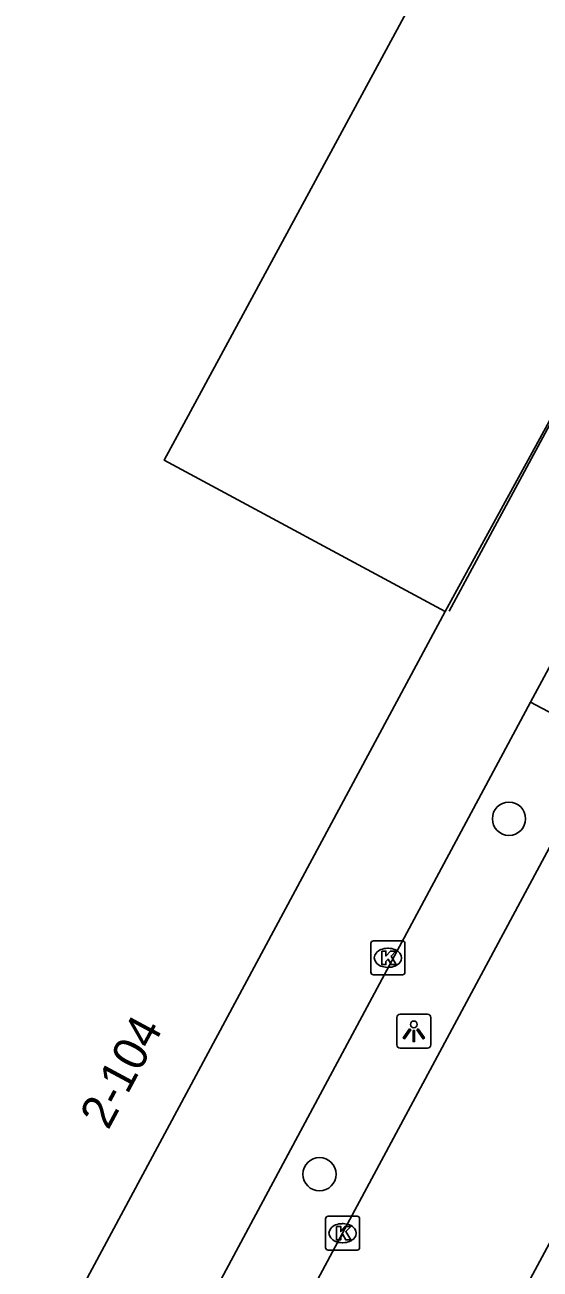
# Model space of a CAD drawing. Extents: x 159489 to 160304, y 383826 to 384530.
# Drawn here: x 159614.71 to 159629.86, y 384181.95 to 384218.51 of the extents above; entities that cross this region are included whole.
import ezdxf

# ---------------------------------------------------------------- set-up
doc = ezdxf.new("R2010")
doc.units = 0
for name, color, linetype in [('IMGEO_Boom', 7, 'Continuous'), ('IMGEO_Kolk', 7, 'Continuous'), ('IMGEO_Lichtpunt', 7, 'Continuous'), ('IMGEO_Lijnafwatering', 7, 'Continuous'), ('IMGEO_Pand', 7, 'Continuous'), ('IMGEO_Pand_nummerreeks', 7, 'Continuous'), ('IMGEO_Rijbaan_lokaal_gesloten', 7, 'Continuous'), ('IMGEO_Voetpad_open', 7, 'Continuous')]:
    doc.layers.add(name, color=color, linetype=linetype)

msp = doc.modelspace()

# ---------------------------------------------------------------- linework, layer by layer
at = {"layer": 'IMGEO_Boom'}
for centre in [(159628.945, 384195.185), (159623.374, 384184.738)]:
    msp.add_circle(centre, 0.489, dxfattribs=at)
at = {"layer": 'IMGEO_Kolk'}
for p, q in [((159624.884, 384190.671), (159624.884, 384191.523)), ((159624.959, 384191.597), (159625.811, 384191.597)), ((159625.372, 384191.377), (159625.397, 384191.377)), ((159625.885, 384191.523), (159625.885, 384190.671)), ((159625.811, 384190.597), (159624.959, 384190.597)), ((159625.395, 384190.817), (159625.37, 384190.817)), ((159623.552, 384182.579), (159623.552, 384183.431)), ((159623.627, 384183.505), (159624.479, 384183.505)), ((159624.04, 384183.285), (159624.065, 384183.285)), ((159624.553, 384183.431), (159624.553, 384182.579)), ((159624.063, 384182.725), (159624.038, 384182.725)), ((159624.479, 384182.505), (159623.627, 384182.505))]:
    msp.add_line(p, q, dxfattribs=at)
for points in [[(159624.884, 384190.671), (159624.884, 384191.523)], [(159624.959, 384191.597), (159625.811, 384191.597)], [(159625.205, 384191.297), (159625.328, 384191.297), (159625.328, 384191.146), (159625.458, 384191.297), (159625.622, 384191.297), (159625.476, 384191.146), (159625.629, 384190.897), (159625.477, 384190.897), (159625.392, 384191.061), (159625.328, 384190.994), (159625.328, 384190.897), (159625.205, 384190.897), (159625.205, 384191.297)], [(159625.885, 384191.523), (159625.885, 384190.671)], [(159625.811, 384190.597), (159624.959, 384190.597)], [(159623.552, 384182.579), (159623.552, 384183.431)], [(159623.627, 384183.505), (159624.479, 384183.505)], [(159624.553, 384183.431), (159624.553, 384182.579)], [(159623.873, 384183.205), (159623.996, 384183.205), (159623.996, 384183.054), (159624.126, 384183.205), (159624.29, 384183.205), (159624.144, 384183.054), (159624.297, 384182.805), (159624.145, 384182.805), (159624.06, 384182.969), (159623.996, 384182.902), (159623.996, 384182.805), (159623.873, 384182.805), (159623.873, 384183.205)], [(159624.479, 384182.505), (159623.627, 384182.505)]]:
    msp.add_lwpolyline(points, dxfattribs=at)
for centre, start, end in [((159624.961, 384191.521), 91.552, 178.448), ((159624.961, 384191.521), 91.552, 178.448), ((159625.809, 384191.521), 1.552, 88.448), ((159625.809, 384191.521), 1.552, 88.448), ((159624.961, 384190.673), 181.552, 268.448), ((159624.961, 384190.673), 181.552, 268.448), ((159625.809, 384190.673), 271.552, 358.448), ((159625.809, 384190.673), 271.552, 358.448), ((159623.629, 384183.429), 91.552, 178.448), ((159623.629, 384183.429), 91.552, 178.448), ((159624.477, 384183.429), 1.552, 88.448), ((159624.477, 384183.429), 1.552, 88.448), ((159623.629, 384182.581), 181.552, 268.448), ((159623.629, 384182.581), 181.552, 268.448), ((159624.477, 384182.581), 271.552, 358.448), ((159624.477, 384182.581), 271.552, 358.448)]:
    msp.add_arc(centre, 0.0765, start, end, dxfattribs=at)
for centre, major_axis, ratio, start_param, end_param in [((159625.371, 384191.097), (-0.387, 0.002), 0.722429, 4.712389, 7.853982), ((159625.396, 384191.097), (-0.39, 0.002), 0.717154, 1.570796, 4.712389), ((159624.039, 384183.005), (-0.387, 0.002), 0.722429, 4.712389, 7.853982), ((159624.064, 384183.005), (-0.39, 0.002), 0.717154, 1.570796, 4.712389)]:
    msp.add_ellipse(centre, major_axis=major_axis, ratio=ratio, start_param=start_param, end_param=end_param, dxfattribs=at)
at = {"layer": 'IMGEO_Lichtpunt'}
for p, q in [((159625.648, 384189.343), (159625.648, 384188.536)), ((159625.648, 384189.343), (159625.648, 384188.536)), ((159626.55, 384189.438), (159625.742, 384189.438)), ((159626.55, 384189.438), (159625.742, 384189.438)), ((159626.644, 384188.536), (159626.644, 384189.343)), ((159626.644, 384188.536), (159626.644, 384189.343)), ((159625.742, 384188.442), (159626.55, 384188.442)), ((159625.742, 384188.442), (159626.55, 384188.442))]:
    msp.add_line(p, q, dxfattribs=at)
for points in [[(159626.022, 384189.007), (159626.061, 384188.979), (159625.873, 384188.717), (159625.835, 384188.744), (159626.022, 384189.007)], [(159626.124, 384188.959), (159626.171, 384188.959), (159626.171, 384188.637), (159626.124, 384188.637), (159626.124, 384188.959)], [(159626.234, 384188.979), (159626.272, 384189.006), (159626.459, 384188.744), (159626.42, 384188.716), (159626.234, 384188.979)]]:
    msp.add_lwpolyline(points, dxfattribs=at)
msp.add_circle((159626.147, 384189.141), 0.0994, dxfattribs=at)
for centre, start, end in [((159625.742, 384189.343), 90, 180), ((159625.742, 384189.343), 90, 180), ((159626.55, 384189.343), 0, 90), ((159626.55, 384189.343), 0, 90), ((159625.742, 384188.536), 180, 270), ((159625.742, 384188.536), 180, 270), ((159626.55, 384188.536), 270, 0), ((159626.55, 384188.536), 270, 360)]:
    msp.add_arc(centre, 0.0946, start, end, dxfattribs=at)
at = {"layer": 'IMGEO_Lijnafwatering'}
msp.add_lwpolyline([(159627.183, 384201.285), (159633.971, 384213.85)], dxfattribs=at)
at = {"layer": 'IMGEO_Pand'}
for points in [[(159627.071, 384201.275), (159618.808, 384205.718), (159623.257, 384213.945), (159629.821, 384226.083), (159614.722, 384234.18), (159602.531, 384211.447), (159601.626, 384209.778), (159609.875, 384205.335), (159596.947, 384181.297), (159611.51, 384173.469)], [(159611.986, 384173.213), (159614.197, 384177.327), (159627.071, 384201.275)]]:
    msp.add_lwpolyline(points, dxfattribs=at)
at = {"layer": 'IMGEO_Rijbaan_lokaal_gesloten'}
for points in [[(159621.259, 384166.179), (159621.791, 384167.209), (159629.16, 384180.893), (159636.525, 384194.583), (159640.934, 384202.788), (159639.307, 384203.695), (159640.5, 384205.922), (159642.138, 384205.059), (159643.404, 384207.416), (159644.131, 384208.747)], [(159631.805, 384197.437), (159631.422, 384196.726), (159624.053, 384183.005), (159617.514, 384170.805)]]:
    msp.add_lwpolyline(points, dxfattribs=at)
at = {"layer": 'IMGEO_Voetpad_open'}
for points in [[(159640.276, 384225.681), (159631.56, 384209.476), (159627.071, 384201.275)], [(159629.581, 384198.613), (159633.141, 384205.225)], [(159617.514, 384170.805), (159615.312, 384172.029), (159629.581, 384198.613)], [(159631.805, 384197.437), (159629.581, 384198.613)]]:
    msp.add_lwpolyline(points, dxfattribs=at)

# ---------------------------------------------------------------- texts
at = {"layer": 'IMGEO_Pand_nummerreeks'}
msp.add_text('2-104', height=1, rotation=61.7305, dxfattribs=at).set_placement((159617.162, 384186.011))

doc.saveas('drawing.dxf')
